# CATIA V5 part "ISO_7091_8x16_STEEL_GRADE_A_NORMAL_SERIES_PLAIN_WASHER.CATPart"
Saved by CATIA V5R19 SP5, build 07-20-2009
Part number: ISO 7091 WASHER 8x16 STEEL GRADE A PLAIN  NORMAL SERIES
Publications: "Mating Face", "Axis"
Bounding box of the stored display mesh (mm): x 0 to 2, y -8 to 8, z -8 to 8
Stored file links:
  Z:\UA\ATLAS\atlascar\ServoPiloto\dir\suportePotenciometro\V2\ISO_7091_8x16_STEEL_GRADE_A_NORMAL_SERIES_PLAIN_WASHER.CATPart
  Z:\programs_vbox\Dassault Systemes\B19\intel_a\startup\components\MechanicalStandardParts\ISO_Standards\Design_Tables\ISO_7091_PLAIN_WASHER_GRADE_C_NORMAL_SERIES.txt
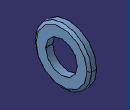
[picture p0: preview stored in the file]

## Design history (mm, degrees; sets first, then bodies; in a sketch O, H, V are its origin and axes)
Parameters
  d1_inside_dia = 9 mm
  d2_outside_dia = 16 mm
  h_max = 2 mm
  Nominal_dia = 8 mm
Body1 "PartBody" (main body)
  Sketch1 on yz-plane, origin (0, 0, 0), H (0, 1, 0), V (0, 0, 1)
    circle A1 centre (0, 0) radius 8
    circle A2 centre (0, 0) radius 4.5
    radius A1 = 8 {= d2_outside_dia /2}
    radius A2 = 4.5 {= d1_inside_dia /2}
  Pad1: profile Sketch1, direction (1, 0, 0), length 2 {= h_max}
  Chamfer1: length 0.75 {= 0.375*h_max}, angle 37.5, on edge [face of Pad1 | face of Pad1]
